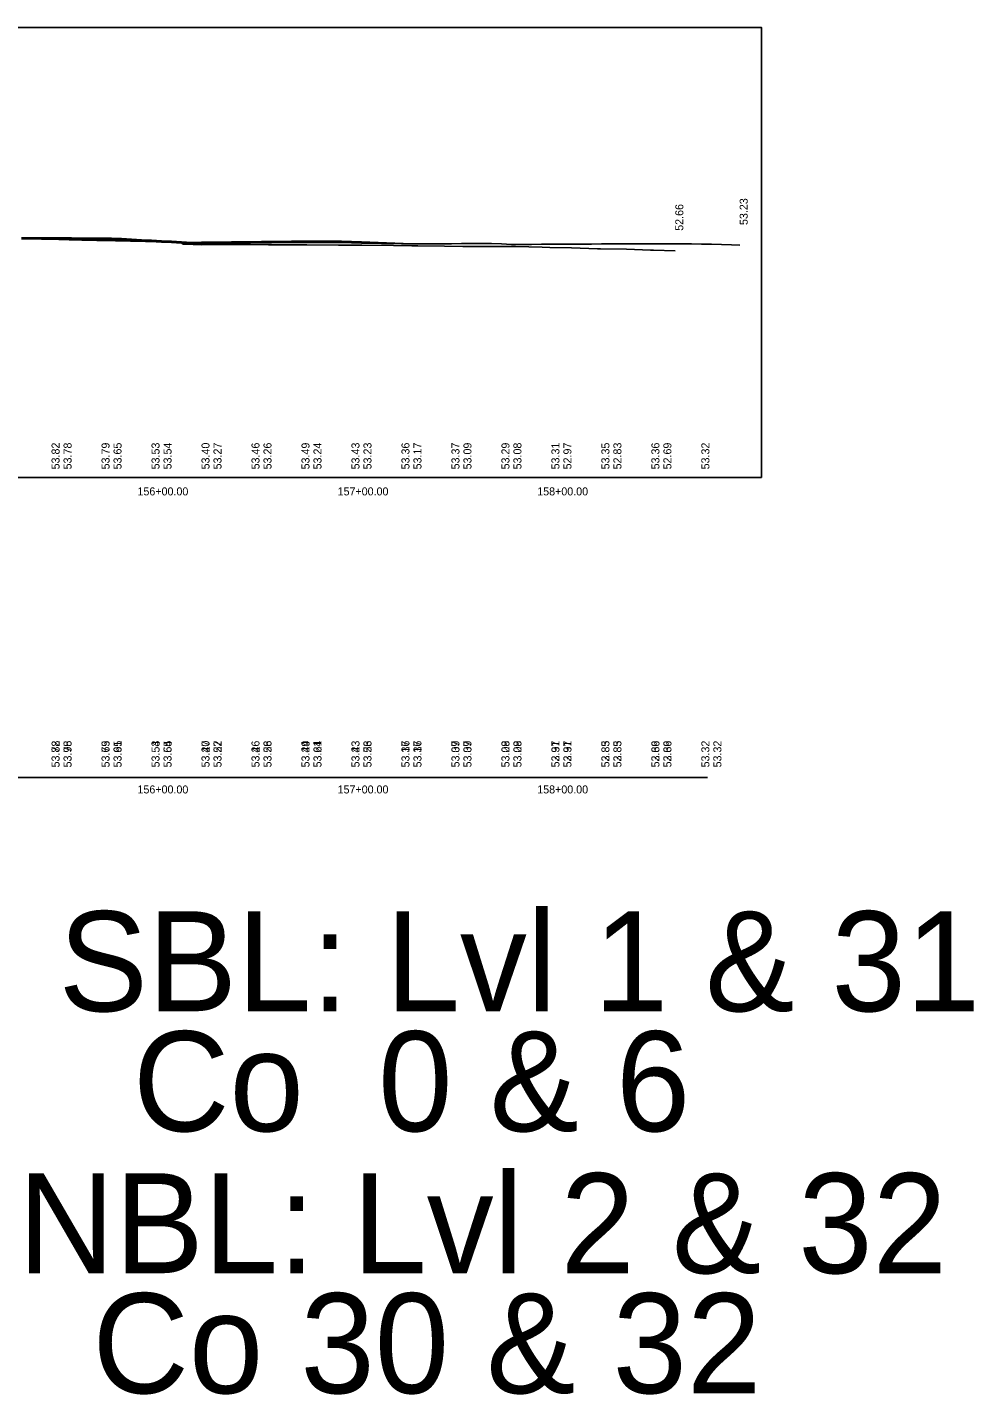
# Model space of a CAD drawing. Extents: x 3880794 to 3915434, y 287517 to 300173.
# Drawn here: x 3896071 to 3896544, y 297416 to 298099 of the extents above; entities that cross this region are included whole.
import ezdxf

# ---------------------------------------------------------------- set-up
doc = ezdxf.new("R2010")
doc.units = 0
for name, color, linetype in [('Level 1', 7, 'Continuous'), ('Level 2', 7, 'Continuous'), ('Level 30', 7, 'Continuous'), ('Level 31', 7, 'Continuous'), ('Level 32', 7, 'Continuous'), ('Level 62', 7, 'Continuous'), ('Level 63', 7, 'Continuous')]:
    doc.layers.add(name, color=color, linetype=linetype)

msp = doc.modelspace()

# ---------------------------------------------------------------- linework, layer by layer
at = {"layer": 'Level 1'}
for p, q in [((3896070.33, 297993.68), (3896076.63, 297993.47)), ((3896076.63, 297993.47), (3896092.18, 297992.96)), ((3896092.18, 297992.96), (3896098.44, 297992.83)), ((3896098.44, 297992.83), (3896105.99, 297992.58)), ((3896105.99, 297992.58), (3896115.2, 297992.38)), ((3896115.2, 297992.38), (3896130.26, 297992.05)), ((3896130.26, 297992.05), (3896140.87, 297991.83)), ((3896140.87, 297991.83), (3896147.93, 297991.67)), ((3896147.93, 297991.67), (3896149.19, 297990.82)), ((3896149.19, 297990.82), (3896149.77, 297990.8)), ((3896149.77, 297990.8), (3896158.28, 297990.52)), ((3896158.28, 297990.52), (3896174.77, 297990.66)), ((3896174.77, 297990.66), (3896177.58, 297990.6)), ((3896177.58, 297990.6), (3896182.72, 297990.64)), ((3896182.72, 297990.64), (3896191.87, 297990.43)), ((3896191.87, 297990.43), (3896207.72, 297990.42)), ((3896207.72, 297990.42), (3896208.72, 297990.42)), ((3896208.72, 297990.42), (3896210.96, 297990.42)), ((3896210.96, 297990.42), (3896226.77, 297990.37)), ((3896226.77, 297990.37), (3896236.02, 297990.37)), ((3896236.02, 297990.37), (3896238.07, 297990.37)), ((3896238.07, 297990.37), (3896238.5, 297990.36)), ((3896238.5, 297990.36), (3896254.3, 297990.2)), ((3896254.3, 297990.2), (3896263.5, 297990.02)), ((3896263.5, 297990.02), (3896266.17, 297989.99)), ((3896266.17, 297989.99), (3896266.48, 297989.99)), ((3896266.48, 297989.99), (3896279.79, 297989.73)), ((3896279.79, 297989.73), (3896289, 297989.66)), ((3896289, 297989.66), (3896290.79, 297989.66)), ((3896290.79, 297989.66), (3896305.31, 297989.59)), ((3896305.31, 297989.59), (3896315.37, 297989.6)), ((3896315.37, 297989.6), (3896328.72, 297989.23)), ((3896328.72, 297989.23), (3896332.48, 297989.15)), ((3896332.48, 297989.15), (3896343.36, 297988.91)), ((3896343.36, 297988.91), (3896356.36, 297988.5)), ((3896356.36, 297988.5), (3896357.79, 297988.45)), ((3896357.79, 297988.45), (3896370.81, 297988.23)), ((3896370.81, 297988.23), (3896382.79, 297987.76)), ((3896382.79, 297987.76), (3896383.38, 297987.74)), ((3896383.38, 297987.74), (3896384.37, 297987.73)), ((3896384.37, 297987.73), (3896395.25, 297987.48))]:
    msp.add_line(p, q, dxfattribs=at)
msp.add_lwpolyline([(3896070.33, 297993.68), (3896076.63, 297993.47), (3896092.18, 297992.96), (3896098.44, 297992.83), (3896105.99, 297992.58), (3896115.2, 297992.38), (3896130.26, 297992.05), (3896140.87, 297991.83), (3896147.93, 297991.67), (3896149.19, 297990.82), (3896149.77, 297990.8), (3896158.28, 297990.52), (3896174.77, 297990.66), (3896177.58, 297990.6), (3896182.72, 297990.64), (3896191.87, 297990.43), (3896207.72, 297990.42), (3896208.72, 297990.42), (3896210.96, 297990.42), (3896226.77, 297990.37), (3896236.02, 297990.37), (3896238.07, 297990.37), (3896238.5, 297990.36), (3896254.3, 297990.2), (3896263.5, 297990.02), (3896266.17, 297989.99), (3896266.48, 297989.99), (3896279.79, 297989.73), (3896289, 297989.66), (3896290.79, 297989.66), (3896305.31, 297989.59), (3896315.37, 297989.6), (3896328.72, 297989.23), (3896332.48, 297989.15), (3896343.36, 297988.91), (3896356.36, 297988.5), (3896357.79, 297988.45), (3896370.81, 297988.23), (3896382.79, 297987.76), (3896383.38, 297987.74), (3896384.37, 297987.73), (3896395.25, 297987.48)], dxfattribs=at)
at = {"layer": 'Level 2'}
for p, q in [((3896068.3, 297994.04), (3896073.3, 297994.01)), ((3896073.3, 297994.01), (3896078.3, 297993.98)), ((3896078.3, 297993.98), (3896083.3, 297993.95)), ((3896083.3, 297993.95), (3896088.3, 297993.92)), ((3896088.3, 297993.92), (3896093.3, 297993.88)), ((3896093.3, 297993.88), (3896098.3, 297993.85)), ((3896098.3, 297993.85), (3896103.3, 297993.82)), ((3896103.3, 297993.82), (3896108.3, 297993.79)), ((3896108.3, 297993.79), (3896113.3, 297993.76)), ((3896113.3, 297993.76), (3896118.3, 297993.62)), ((3896118.3, 297993.62), (3896123.3, 297993.33)), ((3896123.3, 297993.33), (3896128.3, 297993.04)), ((3896128.3, 297993.04), (3896133.3, 297992.74)), ((3896133.3, 297992.74), (3896138.3, 297992.46)), ((3896138.3, 297992.46), (3896143.3, 297992.21)), ((3896143.3, 297992.21), (3896148.3, 297991.91)), ((3896148.3, 297991.91), (3896153.3, 297991.68)), ((3896153.3, 297991.68), (3896158.3, 297991.74)), ((3896158.3, 297991.74), (3896163.3, 297991.8)), ((3896163.3, 297991.8), (3896168.3, 297991.86)), ((3896168.3, 297991.86), (3896173.3, 297991.92)), ((3896173.3, 297991.92), (3896178.3, 297991.99)), ((3896178.3, 297991.99), (3896183.3, 297992.04)), ((3896183.3, 297992.04), (3896188.3, 297992.1)), ((3896188.3, 297992.1), (3896193.3, 297992.15)), ((3896193.3, 297992.15), (3896198.3, 297992.18)), ((3896198.3, 297992.18), (3896203.3, 297992.21)), ((3896203.3, 297992.21), (3896208.3, 297992.25)), ((3896208.3, 297992.25), (3896213.3, 297992.26)), ((3896213.3, 297992.26), (3896218.3, 297992.27)), ((3896218.3, 297992.27), (3896223.3, 297992.28)), ((3896223.3, 297992.28), (3896228.3, 297992.22)), ((3896228.3, 297992.22), (3896233.3, 297992.1)), ((3896233.3, 297992.1), (3896238.3, 297991.97)), ((3896238.3, 297991.97), (3896263.3, 297990.97)), ((3896263.3, 297990.97), (3896268.3, 297990.96)), ((3896268.3, 297990.96), (3896273.3, 297990.98)), ((3896273.3, 297990.98), (3896278.3, 297991.01)), ((3896278.3, 297991.01), (3896283.3, 297991.04)), ((3896283.3, 297991.04), (3896288.3, 297991.05)), ((3896288.3, 297991.05), (3896293.3, 297991.05)), ((3896293.3, 297991.05), (3896298.3, 297991.05)), ((3896298.3, 297991.05), (3896303.3, 297991.07)), ((3896303.3, 297991.07), (3896308.3, 297990.93)), ((3896308.3, 297990.93), (3896313.3, 297990.66)), ((3896313.3, 297990.66), (3896318.3, 297990.68)), ((3896318.3, 297990.68), (3896323.3, 297990.69)), ((3896323.3, 297990.69), (3896328.3, 297990.71)), ((3896328.3, 297990.71), (3896333.3, 297990.73)), ((3896333.3, 297990.73), (3896338.3, 297990.74)), ((3896338.3, 297990.74), (3896343.3, 297990.76)), ((3896343.3, 297990.76), (3896348.3, 297990.81)), ((3896348.3, 297990.81), (3896353.3, 297990.85)), ((3896353.3, 297990.85), (3896358.3, 297990.9)), ((3896358.3, 297990.9), (3896363.3, 297990.94)), ((3896363.3, 297990.94), (3896368.3, 297990.95)), ((3896368.3, 297990.95), (3896373.3, 297990.96)), ((3896373.3, 297990.96), (3896378.3, 297990.97)), ((3896378.3, 297990.97), (3896383.3, 297990.98)), ((3896383.3, 297990.98), (3896388.3, 297990.99)), ((3896388.3, 297990.99), (3896393.3, 297990.97)), ((3896393.3, 297990.97), (3896398.3, 297990.93)), ((3896398.3, 297990.93), (3896403.3, 297990.89)), ((3896403.3, 297990.89), (3896408.3, 297990.85)), ((3896408.3, 297990.85), (3896413.3, 297990.81)), ((3896413.3, 297990.81), (3896418.3, 297990.7)), ((3896418.3, 297990.7), (3896423.3, 297990.51)), ((3896423.3, 297990.51), (3896427.45, 297990.36))]:
    msp.add_line(p, q, dxfattribs=at)
msp.add_lwpolyline([(3896068.3, 297993.42), (3896073.3, 297993.39), (3896078.3, 297993.36), (3896083.3, 297993.32), (3896088.3, 297993.29), (3896093.3, 297993.26), (3896098.3, 297993.22), (3896103.3, 297993.19), (3896108.3, 297993.16), (3896113.3, 297993.13), (3896118.3, 297993), (3896123.3, 297992.71), (3896128.3, 297992.41), (3896133.3, 297992.12), (3896138.3, 297991.82), (3896143.3, 297991.58), (3896148.3, 297991.28), (3896153.3, 297991.06), (3896158.3, 297991.12), (3896163.3, 297991.18), (3896168.3, 297991.24), (3896173.3, 297991.3), (3896178.3, 297991.36), (3896183.3, 297991.42), (3896188.3, 297991.48), (3896193.3, 297991.53), (3896198.3, 297991.55), (3896203.3, 297991.59), (3896208.3, 297991.62), (3896213.3, 297991.63), (3896218.3, 297991.64), (3896223.3, 297991.65), (3896228.3, 297991.6), (3896233.3, 297991.47), (3896238.3, 297991.34), (3896243.3, 297991.21), (3896248.3, 297991.12), (3896253.3, 297991.07), (3896258.3, 297991.02), (3896263.3, 297990.97), (3896268.3, 297990.96), (3896273.3, 297990.98), (3896278.3, 297991.01), (3896283.3, 297991.04), (3896288.3, 297991.05), (3896293.3, 297991.05), (3896298.3, 297991.05), (3896303.3, 297991.07), (3896308.3, 297990.93), (3896313.3, 297990.66), (3896318.3, 297990.68), (3896323.3, 297990.69), (3896328.3, 297990.71), (3896333.3, 297990.73), (3896338.3, 297990.74), (3896343.3, 297990.76), (3896348.3, 297990.81), (3896353.3, 297990.85), (3896358.3, 297990.9), (3896363.3, 297990.94), (3896368.3, 297990.95), (3896373.3, 297990.96), (3896378.3, 297990.97), (3896383.3, 297990.98), (3896388.3, 297990.99), (3896393.3, 297990.97), (3896398.3, 297990.93), (3896403.3, 297990.89), (3896408.3, 297990.85), (3896413.3, 297990.81), (3896418.3, 297990.7), (3896423.3, 297990.51), (3896427.45, 297990.36)], dxfattribs=at)
at = {"layer": 'Level 62'}
msp.add_lwpolyline([(3895738.3, 297874.19), (3896438.3, 297874.19), (3896438.3, 298099.19), (3895738.3, 298099.19)], close=True, dxfattribs=at)
msp.add_lwpolyline([(3895738.3, 297874.19), (3896438.3, 297874.19), (3896438.3, 298099.19), (3895738.3, 298099.19)], close=True, dxfattribs=at)
at = {"layer": 'Level 63'}
msp.add_line((3881538.3, 297724.19), (3896411.35, 297724.19), dxfattribs=at)

# ---------------------------------------------------------------- texts
at = {"layer": 'Level 1'}
for s, p in [('SBL: Lvl 1 & 31', (3896086.86, 297607.3)), ('  Co  0 & 6', (3896086.86, 297547.3))]:
    msp.add_text(s, height=50, dxfattribs=at).set_placement(p)
at = {"layer": 'Level 2'}
msp.add_text('53.23', height=4, rotation=90, dxfattribs=at).set_placement((3896431.45, 298000.36))
for s, p in [('NBL: Lvl 2 & 32', (3896066.56, 297476.33)), ('  Co 30 & 32', (3896066.56, 297416.33))]:
    msp.add_text(s, height=50, dxfattribs=at).set_placement(p)
at = {"layer": 'Level 30'}
for s, p in [('156+00.00', (3896126.27, 297865.19)), ('156+00.00', (3896126.27, 297865.19)), ('157+00.00', (3896226.36, 297865.19)), ('157+00.00', (3896226.36, 297865.19)), ('158+00.00', (3896326.2, 297865.19)), ('158+00.00', (3896326.2, 297865.19)), ('156+00.00', (3896126.27, 297716.19)), ('156+00.00', (3896126.27, 297716.19)), ('157+00.00', (3896226.36, 297716.19)), ('157+00.00', (3896226.36, 297716.19)), ('158+00.00', (3896326.2, 297716.19)), ('158+00.00', (3896326.2, 297716.19))]:
    msp.add_text(s, height=4, dxfattribs=at).set_placement(p)
at = {"layer": 'Level 31'}
for s, p in [('52.66', (3896399.25, 297997.48)), ('53.78', (3896093.3, 297878.19)), ('53.65', (3896118.3, 297878.19)), ('53.54', (3896143.3, 297878.19)), ('53.27', (3896168.3, 297878.19)), ('53.26', (3896193.3, 297878.19)), ('53.24', (3896218.3, 297878.19)), ('53.23', (3896243.3, 297878.19)), ('53.17', (3896268.3, 297878.19)), ('53.09', (3896293.3, 297878.19)), ('53.08', (3896318.3, 297878.19)), ('52.97', (3896343.3, 297878.19)), ('52.83', (3896368.3, 297878.19)), ('52.69', (3896393.3, 297878.19)), ('53.78', (3896087.3, 297729.19)), ('53.78', (3896093.3, 297729.19)), ('53.65', (3896112.3, 297729.19)), ('53.65', (3896118.3, 297729.19)), ('53.54', (3896137.3, 297729.19)), ('53.54', (3896143.3, 297729.19)), ('53.27', (3896162.3, 297729.19)), ('53.27', (3896168.3, 297729.19)), ('53.26', (3896187.3, 297729.19)), ('53.26', (3896193.3, 297729.19)), ('53.24', (3896212.3, 297729.19)), ('53.24', (3896218.3, 297729.19)), ('53.23', (3896237.3, 297729.19)), ('53.23', (3896243.3, 297729.19)), ('53.17', (3896262.3, 297729.19)), ('53.17', (3896268.3, 297729.19)), ('53.09', (3896287.3, 297729.19)), ('53.09', (3896293.3, 297729.19)), ('53.08', (3896312.3, 297729.19)), ('53.08', (3896318.3, 297729.19)), ('52.97', (3896337.3, 297729.19)), ('52.97', (3896343.3, 297729.19)), ('52.83', (3896362.3, 297729.19)), ('52.83', (3896368.3, 297729.19)), ('52.69', (3896387.3, 297729.19)), ('52.69', (3896393.3, 297729.19))]:
    msp.add_text(s, height=4, rotation=90, dxfattribs=at).set_placement(p)
at = {"layer": 'Level 32'}
for s, p in [('53.82', (3896087.3, 297878.19)), ('53.79', (3896112.3, 297878.19)), ('53.53', (3896137.3, 297878.19)), ('53.40', (3896162.3, 297878.19)), ('53.46', (3896187.3, 297878.19)), ('53.49', (3896212.3, 297878.19)), ('53.43', (3896237.3, 297878.19)), ('53.36', (3896262.3, 297878.19)), ('53.37', (3896287.3, 297878.19)), ('53.29', (3896312.3, 297878.19)), ('53.31', (3896337.3, 297878.19)), ('53.35', (3896362.3, 297878.19)), ('53.36', (3896387.3, 297878.19)), ('53.32', (3896412.3, 297878.19)), ('53.82', (3896087.3, 297729.19)), ('53.95', (3896093.3, 297729.19)), ('53.79', (3896112.3, 297729.19)), ('53.91', (3896118.3, 297729.19)), ('53.53', (3896137.3, 297729.19)), ('53.65', (3896143.3, 297729.19)), ('53.40', (3896162.3, 297729.19)), ('53.52', (3896168.3, 297729.19)), ('53.46', (3896187.3, 297729.19)), ('53.58', (3896193.3, 297729.19)), ('53.49', (3896212.3, 297729.19)), ('53.61', (3896218.3, 297729.19)), ('53.43', (3896237.3, 297729.19)), ('53.56', (3896243.3, 297729.19)), ('53.36', (3896262.3, 297729.19)), ('53.36', (3896268.3, 297729.19)), ('53.37', (3896287.3, 297729.19)), ('53.37', (3896293.3, 297729.19)), ('53.29', (3896312.3, 297729.19)), ('53.29', (3896318.3, 297729.19)), ('53.31', (3896337.3, 297729.19)), ('53.31', (3896343.3, 297729.19)), ('53.35', (3896362.3, 297729.19)), ('53.35', (3896368.3, 297729.19)), ('53.36', (3896387.3, 297729.19)), ('53.36', (3896393.3, 297729.19)), ('53.32', (3896412.3, 297729.19)), ('53.32', (3896418.3, 297729.19))]:
    msp.add_text(s, height=4, rotation=90, dxfattribs=at).set_placement(p)

doc.saveas('drawing.dxf')
